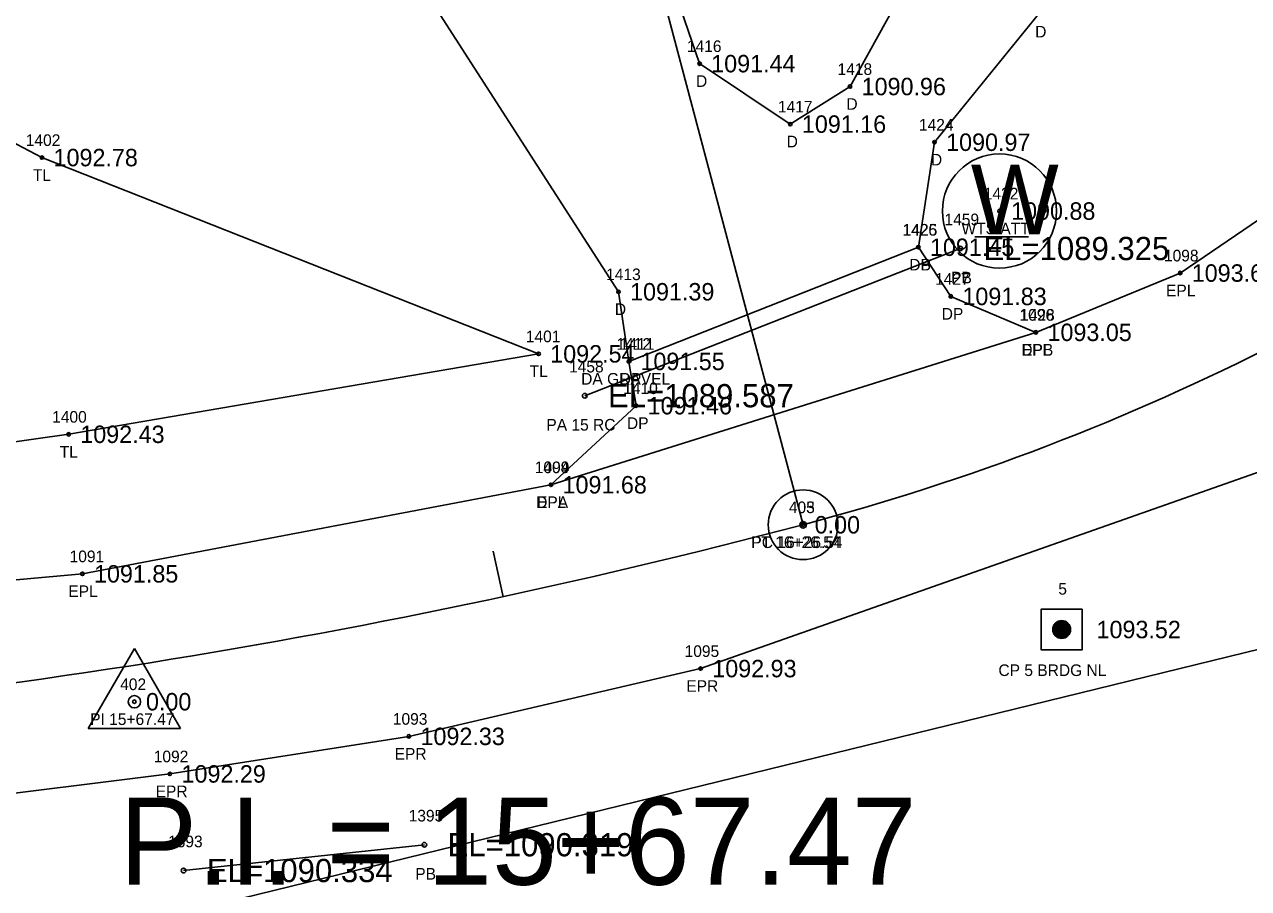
# Model space of a CAD drawing. Extents: x 1539151 to 1541799, y 1198646 to 1201165.
# Drawn here: x 1539950.8 to 1540056.1, y 1199362.7 to 1199437 of the extents above; entities that cross this region are included whole.
import ezdxf

# ---------------------------------------------------------------- set-up
doc = ezdxf.new("R2010")
doc.units = 0
for name, color, linetype in [('RD_EX_DR_Pipe', 7, 'Continuous'), ('RD_EX_DR_Pipe_txCode', 7, 'Continuous'), ('RD_EX_Driveway', 7, 'Continuous'), ('RD_EX_Driveway_txCode', 7, 'Continuous'), ('RD_EX_Road', 7, 'Continuous'), ('RD_EX_Road_txCode', 7, 'Continuous'), ('RD_EX_TX_Driveway_ELEV', 7, 'Continuous'), ('RD_EX_TX_Road_ELEV', 7, 'Continuous'), ('RD_EX_TX_UT_ELEV', 7, 'Continuous'), ('RD_EX_TX_VEG_ELEV', 7, 'Continuous'), ('RD_EX_UT', 7, 'Continuous'), ('RD_EX_UT_txCode', 7, 'Continuous'), ('RD_EX_VEG', 7, 'Continuous'), ('RD_EX_VEG_txCode', 7, 'Continuous'), ('RD_HC_Cl', 7, 'Continuous'), ('RD_HC_Data', 7, 'Continuous'), ('RD_HC_Data_Tic', 7, 'Continuous'), ('RD_HC_Survey', 7, 'Continuous'), ('RD_HC_Survey_ELEV', 7, 'Continuous'), ('RD_HC_Survey_txCode', 7, 'Continuous'), ('RD_HC_txCode', 7, 'Continuous'), ('RD_SMD_Locator', 7, 'Continuous'), ('RD_TX_Pipe_ElevEX', 7, 'Continuous')]:
    doc.layers.add(name, color=color, linetype=linetype)

msp = doc.modelspace()

# ---------------------------------------------------------------- linework, layer by layer
at = {"layer": 'RD_EX_DR_Pipe'}
for p, q in [((1539999.04, 1199405.06), (1540031.34, 1199417.72)), ((1539964.53, 1199364.22), (1539985.24, 1199366.44))]:
    msp.add_line(p, q, dxfattribs=at)
at = {"layer": 'RD_EX_Driveway'}
for points in [[(1540002.83, 1199408.01), (1540001.94, 1199414), (1539983.9, 1199442.03), (1540004.44, 1199446.68), (1540008.92, 1199433.62), (1540016.72, 1199428.42), (1540021.86, 1199431.65), (1540035.27, 1199455.89), (1540042.35, 1199472.58), (1540051.56, 1199472), (1540043.66, 1199450.25), (1540038.09, 1199437.87), (1540029.13, 1199426.86), (1540027.74, 1199417.83)], [(1539996.13, 1199397.4), (1540003.45, 1199404.2), (1540002.83, 1199408.01), (1540027.74, 1199417.83), (1540030.53, 1199413.6), (1540037.85, 1199410.51)]]:
    msp.add_lwpolyline(points, dxfattribs=at)
at = {"layer": 'RD_EX_Road'}
for points in [[(1539428.76, 1199454.93), (1539416.46, 1199395.23), (1539420.91, 1199377.84), (1539428.29, 1199368.53), (1539440.24, 1199363.06), (1539462.84, 1199364.11), (1539506.12, 1199366.59), (1539554.03, 1199368.02), (1539606.53, 1199370.48), (1539651.89, 1199372.76), (1539672.94, 1199372.91), (1539707.02, 1199374.85), (1539748.7, 1199377.62), (1539769.05, 1199378.19), (1539812.94, 1199380.16), (1539830.48, 1199381.23), (1539857.01, 1199382.87), (1539908.22, 1199385.45), (1539955.82, 1199389.74), (1539996.13, 1199397.4), (1540037.85, 1199410.51), (1540050.26, 1199415.61), (1540093.12, 1199444.78)], [(1539925.86, 1199367.85), (1539963.35, 1199372.53), (1539983.91, 1199375.76), (1540009.01, 1199381.59), (1540058.79, 1199399.12), (1540106.31, 1199430.72)]]:
    msp.add_lwpolyline(points, dxfattribs=at)
at = {"layer": 'RD_EX_UT'}
msp.add_line((1540032.59, 1199418.73), (1540037.22, 1199418.73), dxfattribs=at)
msp.add_circle((1540034.72, 1199420.94), 4.91, dxfattribs=at)
at = {"layer": 'RD_EX_VEG'}
for points in [[(1539846.78, 1199470.02), (1539829.4, 1199392.14), (1539911.66, 1199395.68), (1539954.64, 1199401.74), (1539995.07, 1199408.66), (1539952.34, 1199425.54), (1539926.15, 1199439.35), (1539942.46, 1199485.66)], [(1539913.28, 1199258.8), (1539924.81, 1199358.8), (1539963.86, 1199360.44), (1540062.92, 1199384.69), (1540118.75, 1199413.61), (1540135.27, 1199341.7), (1540089.61, 1199284.74)]]:
    msp.add_lwpolyline(points, dxfattribs=at)
at = {"layer": 'RD_HC_Cl'}
for centre, radius, start, end in [((1539965.21, 1199592.77), 205.65, 284.8221, 309.3443), ((1539872.5, 1199943.1), 568.04, 272.8619, 284.8221)]:
    msp.add_arc(centre, radius, start, end, dxfattribs=at)
at = {"layer": 'RD_HC_Data'}
for p, q in [((1540017.82, 1199393.96), (1539986.47, 1199512.4)), ((1539956.32, 1199376.44), (1539960.29, 1199383.32)), ((1539960.29, 1199383.32), (1539964.26, 1199376.44)), ((1539956.32, 1199376.44), (1539964.26, 1199376.44))]:
    msp.add_line(p, q, dxfattribs=at)
for centre, radius in [((1540017.82, 1199393.96), 3), ((1540017.82, 1199393.96), 3), ((1540017.82, 1199393.96), 0.282), ((1540017.82, 1199393.96), 0.282), ((1539960.29, 1199378.74), 0.529)]:
    msp.add_circle(centre, radius, dxfattribs=at)
at = {"layer": 'RD_HC_Data_Tic'}
msp.add_line((1539992.01, 1199387.77), (1539991.17, 1199391.68), dxfattribs=at)
at = {"layer": 'RD_HC_Survey'}
for p, q in [((1540039.32, 1199384.78), (1540039.32, 1199385.13)), ((1540039.34, 1199384.69), (1540039.34, 1199385.22)), ((1540039.37, 1199384.63), (1540039.37, 1199385.28)), ((1540039.39, 1199384.58), (1540039.39, 1199385.33)), ((1540039.42, 1199384.54), (1540039.42, 1199385.37)), ((1540039.44, 1199384.51), (1540039.44, 1199385.4)), ((1540039.47, 1199384.47), (1540039.47, 1199385.44)), ((1540039.49, 1199384.44), (1540039.49, 1199385.47)), ((1540039.52, 1199384.42), (1540039.52, 1199385.49)), ((1540039.54, 1199384.39), (1540039.54, 1199385.52)), ((1540039.57, 1199384.37), (1540039.57, 1199385.54)), ((1540039.59, 1199384.35), (1540039.59, 1199385.56)), ((1540039.61, 1199384.33), (1540039.61, 1199385.58)), ((1540039.64, 1199384.31), (1540039.64, 1199385.59)), ((1540039.66, 1199384.3), (1540039.66, 1199385.61)), ((1540039.69, 1199384.28), (1540039.69, 1199385.63)), ((1540039.71, 1199384.27), (1540039.71, 1199385.64)), ((1540039.74, 1199384.26), (1540039.74, 1199385.65)), ((1540039.76, 1199384.25), (1540039.76, 1199385.66)), ((1540039.79, 1199384.24), (1540039.79, 1199385.67)), ((1540039.81, 1199384.23), (1540039.81, 1199385.68)), ((1540039.84, 1199384.22), (1540039.84, 1199385.69)), ((1540039.86, 1199384.21), (1540039.86, 1199385.7)), ((1540039.89, 1199384.21), (1540039.89, 1199385.7)), ((1540039.91, 1199384.2), (1540039.91, 1199385.71)), ((1540039.94, 1199384.2), (1540039.94, 1199385.71)), ((1540039.96, 1199384.19), (1540039.96, 1199385.72)), ((1540039.99, 1199384.19), (1540039.99, 1199385.72)), ((1540040.01, 1199384.19), (1540040.01, 1199385.72)), ((1540040.04, 1199384.19), (1540040.04, 1199385.72)), ((1540040.06, 1199384.19), (1540040.06, 1199385.72)), ((1540040.09, 1199384.19), (1540040.09, 1199385.72)), ((1540040.11, 1199384.19), (1540040.11, 1199385.72)), ((1540040.13, 1199384.19), (1540040.13, 1199385.72)), ((1540040.16, 1199384.19), (1540040.16, 1199385.72)), ((1540040.18, 1199384.19), (1540040.18, 1199385.72)), ((1540040.21, 1199384.2), (1540040.21, 1199385.71)), ((1540040.23, 1199384.2), (1540040.23, 1199385.71)), ((1540040.26, 1199384.21), (1540040.26, 1199385.7)), ((1540040.28, 1199384.22), (1540040.28, 1199385.69)), ((1540040.31, 1199384.22), (1540040.31, 1199385.69)), ((1540040.33, 1199384.23), (1540040.33, 1199385.68)), ((1540040.36, 1199384.24), (1540040.36, 1199385.67)), ((1540040.38, 1199384.25), (1540040.38, 1199385.66)), ((1540040.41, 1199384.26), (1540040.41, 1199385.64)), ((1540040.43, 1199384.28), (1540040.43, 1199385.63)), ((1540040.46, 1199384.29), (1540040.46, 1199385.62)), ((1540040.48, 1199384.31), (1540040.48, 1199385.6)), ((1540040.51, 1199384.32), (1540040.51, 1199385.59)), ((1540040.53, 1199384.34), (1540040.53, 1199385.57)), ((1540040.56, 1199384.36), (1540040.56, 1199385.55)), ((1540040.58, 1199384.38), (1540040.58, 1199385.53)), ((1540040.6, 1199384.41), (1540040.6, 1199385.5)), ((1540040.63, 1199384.43), (1540040.63, 1199385.48)), ((1540040.65, 1199384.46), (1540040.65, 1199385.45)), ((1540040.68, 1199384.49), (1540040.68, 1199385.42)), ((1540040.7, 1199384.52), (1540040.7, 1199385.39)), ((1540040.73, 1199384.56), (1540040.73, 1199385.35)), ((1540040.75, 1199384.61), (1540040.75, 1199385.3)), ((1540040.78, 1199384.66), (1540040.78, 1199385.25)), ((1540040.8, 1199384.73), (1540040.8, 1199385.18)), ((1540040.83, 1199384.84), (1540040.83, 1199385.07))]:
    msp.add_line(p, q, dxfattribs=at)
msp.add_lwpolyline([(1540041.82, 1199386.7), (1540038.32, 1199386.7), (1540038.32, 1199383.2), (1540041.82, 1199383.2)], close=True, dxfattribs=at)
msp.add_circle((1540040.07, 1199384.95), 0.769, dxfattribs=at)
at = {"layer": 'RD_SMD_Locator'}
for centre, radius in [((1540008.92, 1199433.62), 0.15), ((1540021.86, 1199431.65), 0.15), ((1540016.72, 1199428.42), 0.15), ((1540029.13, 1199426.86), 0.15), ((1539952.34, 1199425.54), 0.15), ((1540034.72, 1199420.94), 0.15), ((1540027.74, 1199417.83), 0.15), ((1540027.74, 1199417.83), 0.15), ((1540031.34, 1199417.72), 0.2), ((1540050.26, 1199415.61), 0.15), ((1540001.94, 1199414), 0.15), ((1540030.53, 1199413.6), 0.15), ((1540037.85, 1199410.51), 0.15), ((1540037.85, 1199410.51), 0.15), ((1539995.07, 1199408.66), 0.15), ((1540002.83, 1199408.01), 0.15), ((1540002.83, 1199408.01), 0.15), ((1539999.04, 1199405.06), 0.2), ((1540003.45, 1199404.2), 0.15), ((1539954.64, 1199401.74), 0.15), ((1539996.13, 1199397.4), 0.15), ((1539996.13, 1199397.4), 0.15), ((1540017.82, 1199393.96), 0.15), ((1540017.82, 1199393.96), 0.15), ((1539955.82, 1199389.74), 0.15), ((1540040.07, 1199384.95), 0.15), ((1540009.01, 1199381.59), 0.15), ((1539960.29, 1199378.74), 0.15), ((1539983.91, 1199375.76), 0.15), ((1539963.35, 1199372.53), 0.15), ((1539985.24, 1199366.44), 0.2), ((1539964.53, 1199364.22), 0.2)]:
    msp.add_circle(centre, radius, dxfattribs=at)

# ---------------------------------------------------------------- texts
at = {"layer": 'RD_EX_DR_Pipe_txCode'}
for s, p in [('1459', (1540029.99, 1199419.72)), ('PB', (1540030.56, 1199414.72)), ('1458', (1539997.69, 1199407.06)), ('PA 15 RC', (1539995.74, 1199402.06)), ('1395', (1539983.89, 1199368.44)), ('1393', (1539963.19, 1199366.22)), ('PB', (1539984.46, 1199363.44))]:
    msp.add_text(s, height=1, dxfattribs=at).set_placement(p)
at = {"layer": 'RD_EX_Driveway_txCode'}
for s, p in [('D', (1540037.79, 1199435.87)), ('1416', (1540007.83, 1199434.62)), ('1418', (1540020.79, 1199432.65)), ('D', (1540008.61, 1199431.62)), ('1417', (1540015.66, 1199429.42)), ('D', (1540021.55, 1199429.65)), ('1424', (1540027.79, 1199427.86)), ('D', (1540016.41, 1199426.42)), ('D', (1540028.82, 1199424.86)), ('1426', (1540026.37, 1199418.83)), ('1425', (1540026.4, 1199418.83)), ('DB', (1540026.96, 1199415.83)), ('DP', (1540026.96, 1199415.83)), ('1413', (1540000.88, 1199415)), ('1427', (1540029.18, 1199414.6)), ('D', (1540001.63, 1199412)), ('DP', (1540029.75, 1199411.6)), ('1428', (1540036.5, 1199411.51)), ('1412', (1540001.77, 1199409.01)), ('1411', (1540002.05, 1199409.01)), ('DPB', (1540036.6, 1199408.51)), ('DA GRAVEL', (1539998.73, 1199406.01)), ('DP', (1540002.05, 1199406.01)), ('1410', (1540002.35, 1199405.2)), ('DP', (1540002.67, 1199402.2)), ('1409', (1539994.74, 1199398.4)), ('DPA', (1539994.86, 1199395.4))]:
    msp.add_text(s, height=1, dxfattribs=at).set_placement(p)
at = {"layer": 'RD_EX_Road_txCode'}
for s, p in [('1098', (1540048.87, 1199416.61)), ('EPL', (1540049.05, 1199413.61)), ('1096', (1540036.44, 1199411.51)), ('EPL', (1540036.64, 1199408.51)), ('1094', (1539994.74, 1199398.4)), ('EPL', (1539994.92, 1199395.4)), ('1091', (1539954.72, 1199390.74)), ('EPL', (1539954.61, 1199387.74)), ('1095', (1540007.63, 1199382.59)), ('EPR', (1540007.78, 1199379.59)), ('1093', (1539982.53, 1199376.76)), ('1092', (1539961.96, 1199373.53)), ('EPR', (1539982.68, 1199373.76)), ('EPR', (1539962.12, 1199370.53))]:
    msp.add_text(s, height=1, dxfattribs=at).set_placement(p)
at = {"layer": 'RD_EX_TX_Driveway_ELEV'}
for s, p in [('1091.44', (1540009.92, 1199432.87)), ('1090.96', (1540022.86, 1199430.9)), ('1091.16', (1540017.72, 1199427.67)), ('1090.97', (1540030.13, 1199426.11)), ('1091.45', (1540028.74, 1199417.08)), ('1091.45', (1540028.74, 1199417.08)), ('1091.39', (1540002.94, 1199413.25)), ('1091.83', (1540031.53, 1199412.85)), ('1093.05', (1540038.85, 1199409.76)), ('1091.55', (1540003.83, 1199407.26)), ('1091.55', (1540003.83, 1199407.26)), ('1091.46', (1540004.45, 1199403.45)), ('1091.68', (1539997.13, 1199396.65))]:
    msp.add_text(s, height=1.5, dxfattribs=at).set_placement(p)
at = {"layer": 'RD_EX_TX_Road_ELEV'}
for s, p in [('1093.64', (1540051.26, 1199414.86)), ('1093.05', (1540038.85, 1199409.76)), ('1091.68', (1539997.13, 1199396.65)), ('1091.85', (1539956.82, 1199388.99)), ('1092.93', (1540010.01, 1199380.84)), ('1092.33', (1539984.91, 1199375.01)), ('1092.29', (1539964.35, 1199371.78))]:
    msp.add_text(s, height=1.5, dxfattribs=at).set_placement(p)
at = {"layer": 'RD_EX_TX_UT_ELEV'}
msp.add_text('1090.88', height=1.5, dxfattribs=at).set_placement((1540035.72, 1199420.19))
at = {"layer": 'RD_EX_TX_VEG_ELEV'}
for s, p in [('1092.78', (1539953.34, 1199424.79)), ('1092.54', (1539996.07, 1199407.91)), ('1092.43', (1539955.64, 1199400.99))]:
    msp.add_text(s, height=1.5, dxfattribs=at).set_placement(p)
at = {"layer": 'RD_EX_UT'}
msp.add_text('W', height=6, dxfattribs=at).set_placement((1540032.25, 1199418.94))
at = {"layer": 'RD_EX_UT_txCode'}
for s, p in [('1432', (1540033.37, 1199421.94)), ('WTS ATT', (1540031.45, 1199418.94))]:
    msp.add_text(s, height=1, dxfattribs=at).set_placement(p)
at = {"layer": 'RD_EX_VEG_txCode'}
for s, p in [('1402', (1539950.95, 1199426.54)), ('TL', (1539951.56, 1199423.54)), ('1401', (1539993.97, 1199409.66)), ('TL', (1539994.3, 1199406.66)), ('1400', (1539953.22, 1199402.74)), ('TL', (1539953.87, 1199399.74))]:
    msp.add_text(s, height=1, dxfattribs=at).set_placement(p)
at = {"layer": 'RD_HC_Data'}
msp.add_text('P.I. = 15+67.47', height=7.5, dxfattribs=at).set_placement((1539959, 1199363))
at = {"layer": 'RD_HC_Survey_ELEV'}
for s, p in [('0.00', (1540018.82, 1199393.21)), ('0.00', (1540018.82, 1199393.21)), ('1093.52', (1540043.07, 1199384.2)), ('0.00', (1539961.29, 1199377.99))]:
    msp.add_text(s, height=1.5, dxfattribs=at).set_placement(p)
at = {"layer": 'RD_HC_Survey_txCode'}
for s, p in [('5', (1540039.78, 1199387.95)), ('CP 5 BRDG NL', (1540034.63, 1199380.95))]:
    msp.add_text(s, height=1, dxfattribs=at).set_placement(p)
at = {"layer": 'RD_HC_txCode'}
for s, p in [('403', (1540016.6, 1199394.96)), ('405', (1540016.6, 1199394.96)), ('PT 16+26.54', (1540013.35, 1199391.96)), ('PC 16+26.54', (1540013.38, 1199391.96)), ('402', (1539959.07, 1199379.74)), ('PI 15+67.47', (1539956.49, 1199376.74))]:
    msp.add_text(s, height=1, dxfattribs=at).set_placement(p)
at = {"layer": 'RD_TX_Pipe_ElevEX'}
for s, p in [('EL=1089.325', (1540033.34, 1199416.72)), ('EL=1089.587', (1540001.04, 1199404.06)), ('EL=1090.319', (1539987.24, 1199365.44)), ('EL=1090.334', (1539966.53, 1199363.22))]:
    msp.add_text(s, height=2, dxfattribs=at).set_placement(p)

doc.saveas('drawing.dxf')
